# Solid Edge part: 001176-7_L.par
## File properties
Last saved by: morva
Revision: 82
Accuracy: 0.990
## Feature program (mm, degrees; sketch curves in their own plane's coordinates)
body "unnamed Body 1"
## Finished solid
Body 1: solid body, 11 faces, 20 edges, 12 vertices.
  Faces by surface: torus 4, plane 3, cylinder 2, spline 2
  Edges by curve: circle 8, spline 8, curve on surface 2, line 2
Bounding box of the edges (mm; curved faces can reach further): 19.272 x 8.772 x 29.328, from (520.0084, 407.0412, -73.2819) to (539.2802, 415.8132, -43.9542).
Cylindrical faces by radius (mm): R3.5 x2
Toroidal faces (ring radius, tube radius in mm): R3 r0.5 x4
Planar faces by outward normal: oblique 3
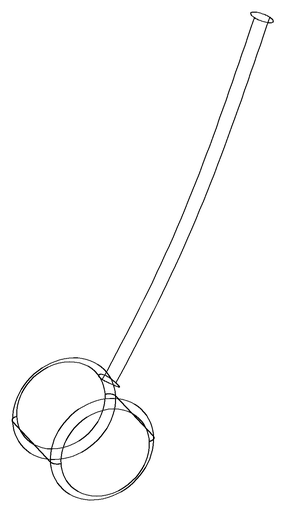
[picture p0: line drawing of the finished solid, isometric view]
